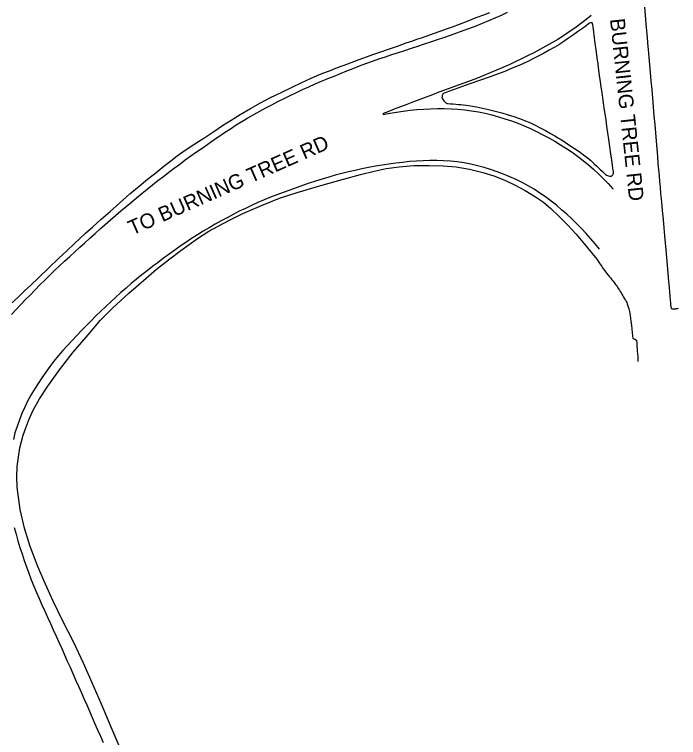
# Model space of a CAD drawing. Extents: x 1948091 to 1975253, y 787267 to 823306.
# Drawn here: x 1964763.1 to 1965005.4, y 804179.4 to 804443.2 of the extents above; entities that cross this region are included whole.
import ezdxf

# ---------------------------------------------------------------- set-up
doc = ezdxf.new("R2010")
doc.units = 0
for name, color, linetype in [('RD_EX_Pavement_Markings', 7, 'Continuous'), ('RD_EX_Road', 7, 'Continuous'), ('RD_TX_RoadID', 7, 'Continuous')]:
    doc.layers.add(name, color=color, linetype=linetype)

msp = doc.modelspace()

# ---------------------------------------------------------------- linework, layer by layer
at = {"layer": 'RD_EX_Pavement_Markings'}
for points in [[(1964761.97, 804333.75), (1964763.67, 804335.58), (1964765.4, 804337.38), (1964767.14, 804339.19), (1964768.89, 804340.97), (1964770.64, 804342.75), (1964772.4, 804344.53), (1964774.18, 804346.29), (1964775.96, 804348.04), (1964777.75, 804349.78), (1964779.58, 804351.49), (1964781.4, 804353.2), (1964783.24, 804354.89), (1964785.09, 804356.58), (1964786.93, 804358.26), (1964788.79, 804359.94), (1964790.64, 804361.62), (1964792.5, 804363.29), (1964794.37, 804364.95), (1964796.23, 804366.61), (1964798.12, 804368.25), (1964800.01, 804369.89), (1964801.91, 804371.51), (1964803.82, 804373.12), (1964805.74, 804374.73), (1964807.66, 804376.33), (1964809.59, 804377.92), (1964811.52, 804379.5), (1964813.48, 804381.06), (1964815.44, 804382.61), (1964817.42, 804384.14), (1964819.41, 804385.65), (1964821.4, 804387.16), (1964823.41, 804388.64), (1964825.43, 804390.12), (1964827.46, 804391.58), (1964829.49, 804393.04), (1964831.53, 804394.48), (1964833.58, 804395.91), (1964835.64, 804397.34), (1964837.71, 804398.74), (1964839.77, 804400.14), (1964841.86, 804401.52), (1964843.95, 804402.89), (1964846.09, 804404.19), (1964848.24, 804405.46), (1964850.4, 804406.71), (1964852.59, 804407.92), (1964854.78, 804409.13), (1964857, 804410.28), (1964859.22, 804411.43), (1964861.45, 804412.55), (1964863.69, 804413.66), (1964865.94, 804414.76), (1964868.22, 804415.79), (1964870.49, 804416.82), (1964872.78, 804417.84), (1964875.06, 804418.86), (1964877.37, 804419.8), (1964879.69, 804420.75), (1964882, 804421.69), (1964884.32, 804422.63), (1964886.64, 804423.55), (1964888.98, 804424.44), (1964891.32, 804425.32), (1964893.67, 804426.18), (1964896.04, 804426.98), (1964898.41, 804427.77), (1964900.78, 804428.56), (1964903.16, 804429.33), (1964905.54, 804430.1), (1964907.92, 804430.87), (1964910.29, 804431.65), (1964912.66, 804432.44), (1964915.03, 804433.24), (1964917.4, 804434.03), (1964919.77, 804434.84), (1964922.13, 804435.66), (1964924.49, 804436.48), (1964926.85, 804437.31), (1964929.2, 804438.16), (1964931.53, 804439.08), (1964933.84, 804440.02), (1964936.15, 804440.97), (1964938.44, 804441.99), (1964940.72, 804443.01), (1964942.98, 804444.07)], [(1964973.46, 804442.85), (1964971.51, 804441.28), (1964969.54, 804439.74), (1964967.53, 804438.26), (1964965.47, 804436.84), (1964963.4, 804435.45), (1964961.27, 804434.13), (1964959.14, 804432.83), (1964956.97, 804431.58), (1964954.77, 804430.41), (1964952.55, 804429.26), (1964950.31, 804428.13), (1964948.08, 804427.02), (1964945.82, 804425.94), (1964943.56, 804424.87), (1964941.27, 804423.86), (1964938.98, 804422.88), (1964936.67, 804421.92), (1964934.35, 804420.97), (1964932.04, 804420.02), (1964929.7, 804419.15), (1964927.35, 804418.29), (1964925, 804417.43), (1964922.66, 804416.57), (1964920.31, 804415.7), (1964917.97, 804414.83), (1964915.63, 804413.94), (1964913.29, 804413.06), (1964910.96, 804412.17), (1964908.62, 804411.28), (1964906.29, 804410.39), (1964903.95, 804409.49), (1964901.62, 804408.6), (1964899.28, 804407.7), (1964897.39, 804406.98)], [(1964897.56, 804406.68), (1964900.01, 804407.15), (1964902.48, 804407.59), (1964904.95, 804407.97), (1964907.43, 804408.26), (1964909.92, 804408.49), (1964912.41, 804408.69), (1964914.91, 804408.81), (1964917.41, 804408.89), (1964919.91, 804408.91), (1964922.4, 804408.81), (1964924.9, 804408.64), (1964927.39, 804408.4), (1964929.87, 804408.1), (1964932.34, 804407.71), (1964934.78, 804407.16), (1964937.2, 804406.56), (1964939.62, 804405.91), (1964942.01, 804405.18), (1964944.37, 804404.37), (1964946.72, 804403.5), (1964949.03, 804402.54), (1964951.32, 804401.54), (1964953.58, 804400.47), (1964955.81, 804399.35), (1964958.03, 804398.19), (1964960.2, 804396.97), (1964962.35, 804395.68), (1964964.45, 804394.33), (1964966.51, 804392.91), (1964968.55, 804391.46), (1964970.52, 804389.93), (1964972.46, 804388.36), (1964974.35, 804386.72), (1964976.2, 804385.03), (1964977.99, 804383.29), (1964979.71, 804381.48), (1964981.34, 804379.58), (1964981.45, 804379.45)], [(1964976.56, 804357.57), (1964974.97, 804359.5), (1964973.34, 804361.39), (1964971.65, 804363.24), (1964969.94, 804365.06), (1964968.2, 804366.85), (1964966.4, 804368.59), (1964964.57, 804370.29), (1964962.7, 804371.95), (1964960.8, 804373.57), (1964958.84, 804375.13), (1964956.84, 804376.62), (1964954.79, 804378.06), (1964952.71, 804379.43), (1964950.56, 804380.71), (1964948.35, 804381.88), (1964946.09, 804382.95), (1964943.8, 804383.95), (1964941.48, 804384.9), (1964939.16, 804385.81), (1964936.79, 804386.61), (1964934.4, 804387.34), (1964931.99, 804388.01), (1964929.55, 804388.57), (1964927.1, 804389.04), (1964924.63, 804389.42), (1964922.14, 804389.67), (1964919.64, 804389.8), (1964917.14, 804389.88), (1964914.64, 804389.92), (1964912.15, 804389.85), (1964909.65, 804389.71), (1964907.16, 804389.51), (1964904.67, 804389.22), (1964902.19, 804388.93), (1964899.72, 804388.58), (1964897.24, 804388.23), (1964894.78, 804387.81), (1964892.31, 804387.38), (1964889.87, 804386.85), (1964887.43, 804386.33), (1964884.99, 804385.75), (1964882.56, 804385.16), (1964880.14, 804384.54), (1964877.73, 804383.9), (1964875.33, 804383.17), (1964872.95, 804382.41), (1964870.58, 804381.63), (1964868.21, 804380.81), (1964865.85, 804379.99), (1964863.5, 804379.14), (1964861.16, 804378.28), (1964858.82, 804377.39), (1964856.49, 804376.49), (1964854.18, 804375.54), (1964851.88, 804374.56), (1964849.6, 804373.53), (1964847.33, 804372.47), (1964845.08, 804371.38), (1964842.87, 804370.22), (1964840.66, 804369.06), (1964838.46, 804367.86), (1964836.27, 804366.66), (1964834.11, 804365.4), (1964831.95, 804364.14), (1964829.84, 804362.8), (1964827.73, 804361.46), (1964825.66, 804360.06), (1964823.59, 804358.66), (1964821.55, 804357.2), (1964819.52, 804355.75), (1964817.51, 804354.26), (1964815.51, 804352.76), (1964813.51, 804351.26), (1964811.54, 804349.72), (1964809.59, 804348.17), (1964807.66, 804346.58), (1964805.72, 804344.99), (1964803.83, 804343.36), (1964801.94, 804341.72), (1964800.06, 804340.07), (1964798.22, 804338.38), (1964796.38, 804336.7), (1964794.57, 804334.97), (1964792.77, 804333.23), (1964791.02, 804331.45), (1964789.27, 804329.66), (1964787.54, 804327.86), (1964785.82, 804326.05), (1964784.09, 804324.24), (1964782.4, 804322.4), (1964780.72, 804320.55), (1964779.09, 804318.66), (1964777.5, 804316.73), (1964775.96, 804314.76), (1964774.5, 804312.73), (1964773.08, 804310.67), (1964771.7, 804308.59), (1964770.39, 804306.46), (1964769.09, 804304.33), (1964767.89, 804302.13), (1964766.83, 804299.87), (1964765.78, 804297.6), (1964764.89, 804295.27), (1964764.04, 804292.92), (1964763.29, 804290.54), (1964762.74, 804288.1)], [(1964763, 804255.97), (1964763.67, 804253.56), (1964764.37, 804251.16), (1964765.08, 804248.77), (1964765.86, 804246.4), (1964766.64, 804244.02), (1964767.47, 804241.67), (1964768.3, 804239.31), (1964769.14, 804236.96), (1964770.11, 804234.66), (1964771.1, 804232.36), (1964772.1, 804230.08), (1964773.13, 804227.8), (1964774.17, 804225.53), (1964775.2, 804223.26), (1964776.23, 804220.98), (1964777.26, 804218.71), (1964778.29, 804216.43), (1964779.32, 804214.15), (1964780.35, 804211.88), (1964781.37, 804209.6), (1964782.38, 804207.31), (1964783.39, 804205.03), (1964784.4, 804202.75), (1964785.41, 804200.46), (1964786.42, 804198.18), (1964787.43, 804195.89), (1964788.44, 804193.61), (1964789.44, 804191.32), (1964790.44, 804189.03), (1964791.44, 804186.74), (1964792.43, 804184.45), (1964793.43, 804182.16), (1964794.43, 804179.87), (1964795.43, 804177.58)]]:
    msp.add_lwpolyline(points, dxfattribs=at)
at = {"layer": 'RD_EX_Road'}
for points in [[(1964992.89, 804445.95), (1964993.45, 804439.79), (1964993.92, 804434.65), (1964994.21, 804431.42), (1964994.29, 804430.54), (1964994.57, 804427.45), (1964994.81, 804424.8), (1964995.05, 804421.99), (1964995.31, 804419.01), (1964995.58, 804415.88), (1964995.85, 804412.67), (1964996.13, 804409.47), (1964996.4, 804406.28), (1964996.68, 804403.1), (1964996.95, 804399.98), (1964997.2, 804397), (1964997.44, 804394.15), (1964997.65, 804391.43), (1964997.86, 804388.86), (1964998.06, 804386.48), (1964998.24, 804384.3), (1964998.41, 804382.3), (1964998.6, 804380.2), (1964998.83, 804377.73), (1964999.09, 804374.89), (1964999.39, 804371.67), (1964999.7, 804368.38), (1964999.98, 804365.32), (1965000.24, 804362.48), (1965000.47, 804359.87), (1965000.7, 804357.3), (1965000.95, 804354.58), (1965001.21, 804351.7), (1965001.48, 804348.67), (1965001.73, 804345.85), (1965001.93, 804343.59), (1965002.08, 804341.89), (1965002.17, 804340.75), (1965002.23, 804339.95), (1965002.29, 804339.26), (1965002.33, 804338.7), (1965002.37, 804338.25), (1965002.41, 804337.88), (1965002.44, 804337.52), (1965002.48, 804337.2), (1965002.51, 804336.89), (1965002.55, 804336.62), (1965002.59, 804336.39), (1965002.63, 804336.2), (1965002.69, 804336.04), (1965002.78, 804335.93), (1965002.92, 804335.85), (1965003.13, 804335.8), (1965003.4, 804335.79), (1965003.68, 804335.79), (1965003.93, 804335.81), (1965004.15, 804335.82), (1965004.34, 804335.85), (1965004.53, 804335.88), (1965004.76, 804335.92), (1965005.04, 804335.98), (1965005.36, 804336.05)], [(1964762.24, 804338.04), (1964765.16, 804340.79), (1964766.79, 804342.32), (1964769.02, 804344.4), (1964771.98, 804347.24), (1964775.64, 804350.81), (1964779.14, 804354.17), (1964782.29, 804357.14), (1964784.82, 804359.51), (1964786.82, 804361.37), (1964789.05, 804363.38), (1964791.64, 804365.67), (1964794.62, 804368.34), (1964797.96, 804371.35), (1964801.51, 804374.52), (1964805.16, 804377.73), (1964808.54, 804380.59), (1964811.62, 804383.07), (1964814.64, 804385.47), (1964817.6, 804387.81), (1964820.15, 804389.84), (1964822.41, 804391.62), (1964825.33, 804393.67), (1964828.95, 804396.01), (1964832.5, 804398.33), (1964835.84, 804400.56), (1964839.02, 804402.66), (1964842.11, 804404.66), (1964845.49, 804406.74), (1964849.18, 804408.9), (1964852.87, 804410.95), (1964856.52, 804412.86), (1964860.38, 804414.78), (1964864.38, 804416.68), (1964867.98, 804418.38), (1964871.06, 804419.85), (1964873.55, 804420.95), (1964875.57, 804421.74), (1964877.98, 804422.66), (1964880.97, 804423.8), (1964884.68, 804425.2), (1964888.86, 804426.75), (1964891.92, 804427.89), (1964893.88, 804428.62), (1964896.37, 804429.48), (1964899.56, 804430.56), (1964902.86, 804431.69), (1964906.05, 804432.8), (1964908.39, 804433.61), (1964909.92, 804434.14), (1964911.61, 804434.73), (1964913.61, 804435.44), (1964915.92, 804436.26), (1964918.45, 804437.15), (1964920.75, 804437.97), (1964922.86, 804438.72), (1964925.46, 804439.7), (1964928.56, 804440.92), (1964931.59, 804442.08), (1964934.38, 804443.12), (1964936.47, 804443.91)], [(1964802.01, 804174.67), (1964798.42, 804183.15), (1964794.83, 804191.59), (1964791.47, 804199.38), (1964788.3, 804206.59), (1964784.73, 804214.08), (1964780.78, 804221.89), (1964777.12, 804229.42), (1964773.93, 804236.39), (1964771.6, 804241.75), (1964768.87, 804249.05), (1964766.81, 804255.77), (1964765.21, 804262.63), (1964764.08, 804270.78), (1964763.94, 804274.52), (1964764.07, 804278.24), (1964765.06, 804285.13), (1964766.31, 804289.75), (1964767.19, 804292.33), (1964768.38, 804295.27), (1964769.93, 804298.83), (1964772.24, 804302.99), (1964775.26, 804307.57), (1964779.55, 804313.56), (1964784.52, 804319.98), (1964789.95, 804326.38), (1964794.52, 804331.66), (1964798.99, 804336.21), (1964804.87, 804341.56), (1964810.14, 804346.13), (1964814.93, 804350.24), (1964819.29, 804353.71), (1964823.76, 804357.1), (1964829.86, 804361.44), (1964834.02, 804364.13), (1964837.4, 804366.01), (1964841.5, 804368.2), (1964846.35, 804370.6), (1964853.16, 804373.49), (1964859.83, 804376.13), (1964866.17, 804378.27), (1964874.92, 804380.85), (1964883.1, 804383.13), (1964889.35, 804384.82), (1964894.37, 804386.05), (1964898.74, 804386.95), (1964903.5, 804387.67), (1964908.83, 804388.09), (1964914.34, 804388.15), (1964919.52, 804387.98), (1964924.27, 804387.58), (1964929.05, 804386.77), (1964933.98, 804385.55), (1964938.01, 804384.32), (1964941.97, 804382.72), (1964945.74, 804380.98), (1964949.39, 804379.01), (1964953.23, 804376.7), (1964956.11, 804374.67), (1964958.82, 804372.39), (1964961.83, 804369.52), (1964964.85, 804366.5), (1964967.99, 804363.02), (1964971.05, 804359.38), (1964973.82, 804356.01), (1964975.51, 804353.89), (1964976.01, 804353.22), (1964976.43, 804352.62), (1964976.79, 804352.1), (1964977.08, 804351.64), (1964977.35, 804351.21), (1964977.66, 804350.75), (1964978.02, 804350.26), (1964978.41, 804349.75), (1964978.83, 804349.22), (1964979.26, 804348.68), (1964979.7, 804348.12), (1964980.16, 804347.54), (1964980.61, 804346.97), (1964981.05, 804346.41), (1964981.47, 804345.88), (1964981.88, 804345.36), (1964982.26, 804344.86), (1964982.62, 804344.39), (1964982.94, 804343.94), (1964983.23, 804343.5), (1964983.51, 804343.07), (1964983.8, 804342.61), (1964984.09, 804342.13), (1964984.39, 804341.62), (1964984.7, 804341.1), (1964985.01, 804340.57), (1964985.34, 804340.04), (1964985.67, 804339.5), (1964985.99, 804338.98), (1964986.26, 804338.5), (1964986.48, 804338.06), (1964986.65, 804337.65), (1964986.79, 804337.28), (1964986.92, 804336.91), (1964987.04, 804336.56), (1964987.14, 804336.22), (1964987.24, 804335.84), (1964987.34, 804335.36), (1964987.45, 804334.8), (1964987.57, 804334.14), (1964987.69, 804333.34), (1964987.83, 804332.35), (1964987.98, 804331.18), (1964988.15, 804329.81), (1964988.31, 804328.42), (1964988.46, 804327.15), (1964988.58, 804326), (1964988.68, 804324.98), (1964989.37, 804324.7), (1964990.04, 804324.43), (1964990.13, 804323.17), (1964990.2, 804322.2), (1964990.28, 804321.05), (1964990.32, 804320.33), (1964990.39, 804319.34), (1964990.45, 804318.42), (1964990.57, 804316.63)]]:
    msp.add_lwpolyline(points, dxfattribs=at)
msp.add_lwpolyline([(1964973.56, 804440.19), (1964973.27, 804440.14), (1964972.92, 804439.98), (1964972.54, 804439.75), (1964971.66, 804439.09), (1964970.33, 804438.12), (1964968.56, 804436.87), (1964966.69, 804435.57), (1964964.83, 804434.29), (1964963.15, 804433.15), (1964961.66, 804432.15), (1964960.03, 804431.15), (1964958.2, 804430.12), (1964955.91, 804428.88), (1964953.18, 804427.45), (1964950.34, 804426.06), (1964947.47, 804424.75), (1964944.7, 804423.56), (1964941.94, 804422.44), (1964938.57, 804421.16), (1964936.61, 804420.45), (1964932.72, 804419.06), (1964929.27, 804417.84), (1964926.21, 804416.76), (1964923.52, 804415.8), (1964921.43, 804415.06), (1964920.19, 804414.61), (1964919.83, 804414.45), (1964919.55, 804414.29), (1964919.35, 804414.12), (1964919.24, 804413.94), (1964919.18, 804413.75), (1964919.13, 804413.56), (1964919.07, 804413.15), (1964919.06, 804412.94), (1964919.09, 804412.74), (1964919.15, 804412.56), (1964919.23, 804412.39), (1964919.47, 804412.04), (1964919.76, 804411.67), (1964920.1, 804411.3), (1964920.47, 804410.98), (1964920.69, 804410.84), (1964920.98, 804410.74), (1964921.34, 804410.67), (1964922.21, 804410.61), (1964923.15, 804410.55), (1964924.12, 804410.49), (1964925.04, 804410.41), (1964925.91, 804410.33), (1964926.83, 804410.22), (1964927.89, 804410.07), (1964929.49, 804409.83), (1964931.62, 804409.48), (1964933.81, 804409.06), (1964936.02, 804408.57), (1964938.41, 804407.97), (1964940.95, 804407.28), (1964943.23, 804406.62), (1964945.25, 804405.99), (1964947.33, 804405.27), (1964949.47, 804404.45), (1964951.38, 804403.64), (1964953.07, 804402.83), (1964954.86, 804401.9), (1964956.79, 804400.84), (1964958.6, 804399.82), (1964960.24, 804398.87), (1964961.58, 804398.1), (1964962.68, 804397.44), (1964964.06, 804396.56), (1964965.76, 804395.44), (1964967.45, 804394.29), (1964969.08, 804393.16), (1964970.67, 804392.01), (1964972.16, 804390.87), (1964973.23, 804390), (1964973.88, 804389.39), (1964974.63, 804388.67), (1964975.52, 804387.82), (1964976.23, 804387.13), (1964976.77, 804386.62), (1964977.44, 804385.98), (1964978.22, 804385.25), (1964978.74, 804384.79), (1964978.87, 804384.69), (1964978.97, 804384.62), (1964979.09, 804384.56), (1964979.41, 804384.45), (1964979.78, 804384.34), (1964980.17, 804384.26), (1964980.51, 804384.21), (1964980.71, 804384.2), (1964980.8, 804384.22), (1964980.93, 804384.27), (1964981.28, 804384.52), (1964981.43, 804384.7), (1964981.51, 804384.9), (1964981.57, 804385.08), (1964981.61, 804385.24), (1964981.63, 804385.41), (1964981.62, 804385.64), (1964981.59, 804385.94), (1964981.54, 804386.3), (1964981.44, 804386.98), (1964981.26, 804388.22), (1964981.01, 804390.02), (1964980.69, 804392.39), (1964980.32, 804395), (1964979.96, 804397.56), (1964979.6, 804400.05), (1964979.25, 804402.48), (1964978.9, 804404.81), (1964978.58, 804407), (1964978.28, 804409.05), (1964978, 804410.97), (1964977.74, 804412.84), (1964977.46, 804414.76), (1964977.17, 804416.73), (1964976.88, 804418.75), (1964976.58, 804420.82), (1964976.28, 804422.94), (1964975.98, 804425.11), (1964975.69, 804427.34), (1964975.41, 804429.43), (1964975.18, 804431.19), (1964974.98, 804432.64), (1964974.83, 804433.76), (1964974.7, 804434.73), (1964974.56, 804435.73), (1964974.43, 804436.75), (1964974.3, 804437.79), (1964974.18, 804438.71), (1964974.08, 804439.39), (1964974, 804439.83), (1964973.94, 804440.01), (1964973.89, 804440.07), (1964973.81, 804440.13), (1964973.71, 804440.18)], close=True, dxfattribs=at)

# ---------------------------------------------------------------- texts
at = {"layer": 'RD_TX_RoadID'}
for s, rotation, p in [('BURNING TREE RD', 276.0604, (1964980.34, 804441.51)), ('TO BURNING TREE RD', 23.8134, (1964806.05, 804362.53))]:
    msp.add_text(s, height=5.4, rotation=rotation, dxfattribs=at).set_placement(p)

doc.saveas('drawing.dxf')
